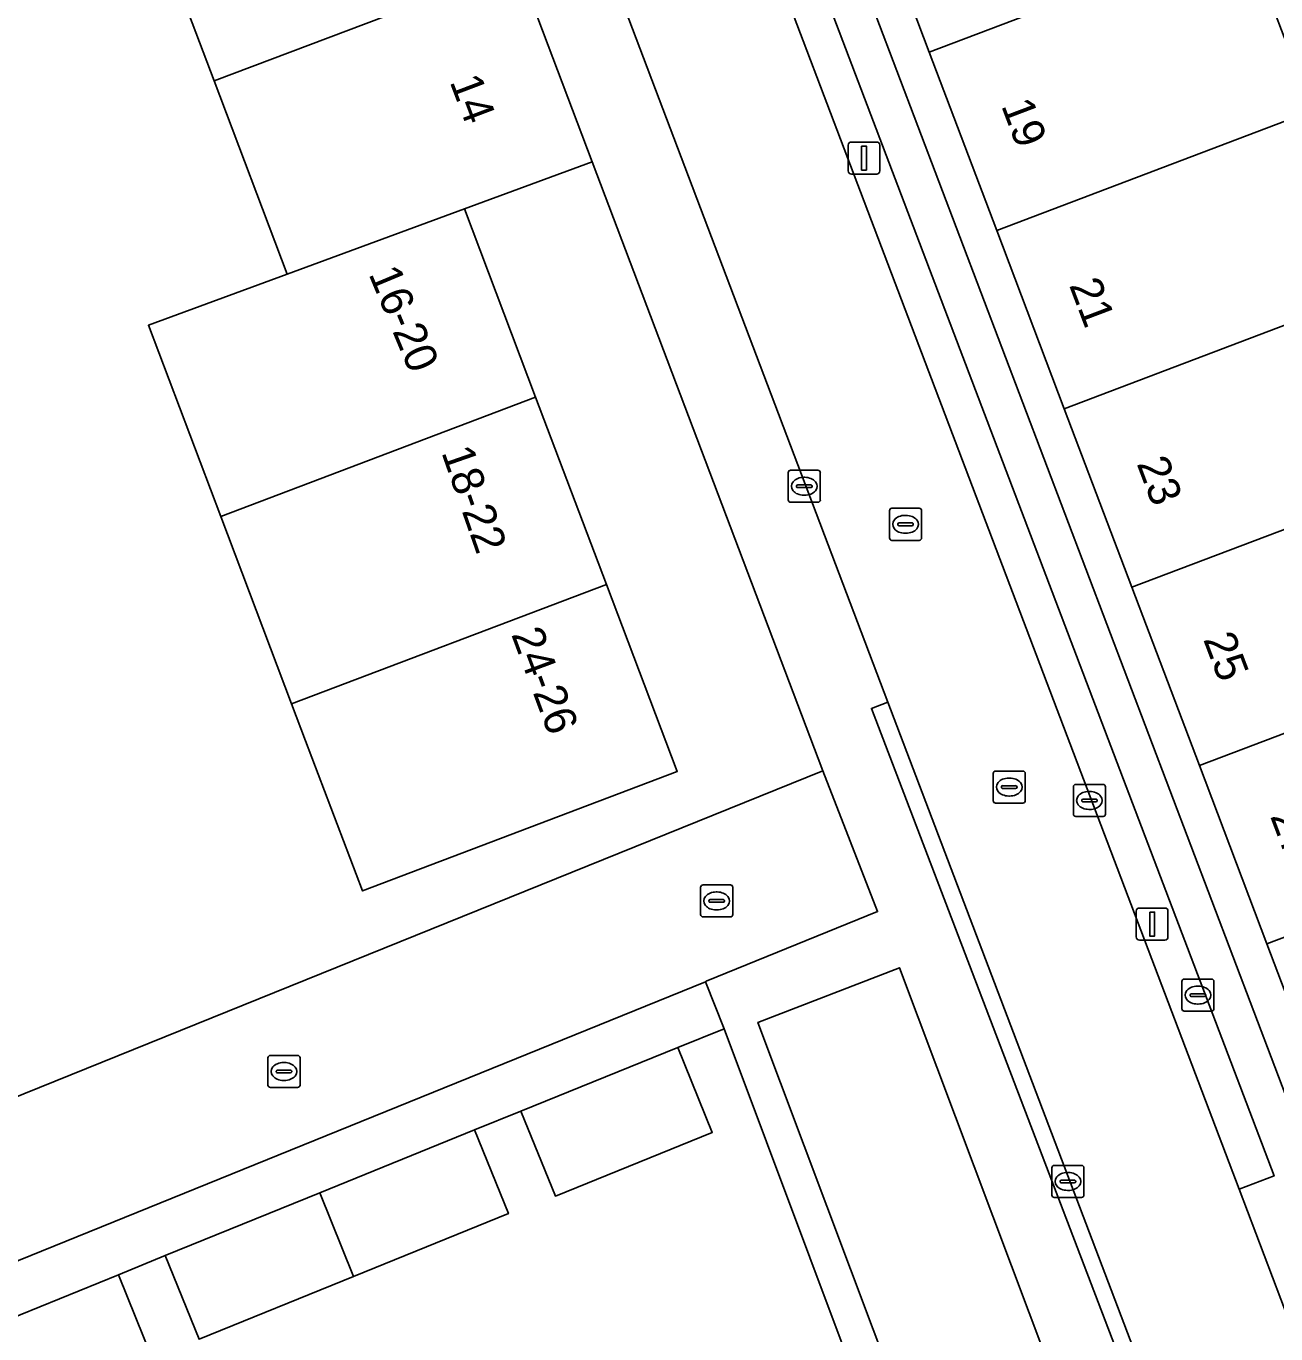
# Model space of a CAD drawing. Extents: x 162989 to 165008, y 383432 to 384338.
# Drawn here: x 163905.52 to 163944.51, y 384017.83 to 384058.61 of the extents above; entities that cross this region are included whole.
import ezdxf

# ---------------------------------------------------------------- set-up
doc = ezdxf.new("R2010")
doc.units = 0
for name, color, linetype in [('IMGEO_Brandkraan', 7, 'Continuous'), ('IMGEO_Erf', 7, 'Continuous'), ('IMGEO_Groenvoorziening', 7, 'Continuous'), ('IMGEO_Kolk', 7, 'Continuous'), ('IMGEO_Lichtmast', 7, 'Continuous'), ('IMGEO_Pand', 7, 'Continuous'), ('IMGEO_Pand_nummerreeks', 7, 'Continuous'), ('IMGEO_Parkeervlak_open', 7, 'Continuous'), ('IMGEO_Rijbaan_lokaal_open', 7, 'Continuous'), ('IMGEO_Rioolput', 7, 'Continuous'), ('IMGEO_Voetpad_open', 7, 'Continuous')]:
    doc.layers.add(name, color=color, linetype=linetype)

msp = doc.modelspace()

# ---------------------------------------------------------------- linework, layer by layer
at = {"layer": 'IMGEO_Brandkraan'}
for p, q in [((163941.655, 384028.894), (163942.507, 384028.894)), ((163941.58, 384027.968), (163941.58, 384028.82)), ((163941.882, 384028.437), (163942.28, 384028.437)), ((163942.068, 384028.674), (163942.093, 384028.674)), ((163942.581, 384028.82), (163942.581, 384027.968)), ((163941.839, 384028.388), (163941.839, 384028.4)), ((163942.277, 384028.351), (163941.879, 384028.351)), ((163942.091, 384028.114), (163942.066, 384028.114)), ((163942.323, 384028.4), (163942.323, 384028.388)), ((163942.507, 384027.894), (163941.655, 384027.894))]:
    msp.add_line(p, q, dxfattribs=at)
for points in [[(163941.655, 384028.894), (163942.507, 384028.894)], [(163941.58, 384027.968), (163941.58, 384028.82)], [(163942.581, 384028.82), (163942.581, 384027.968)], [(163942.507, 384027.894), (163941.655, 384027.894)]]:
    msp.add_lwpolyline(points, dxfattribs=at)
for centre, radius, start, end in [((163941.657, 384028.818), 0.0765, 91.552, 178.448), ((163941.657, 384028.818), 0.0765, 91.552, 178.448), ((163942.505, 384028.818), 0.0765, 1.552, 88.448), ((163942.505, 384028.818), 0.0765, 1.552, 88.448), ((163941.879, 384028.397), 0.0403, 85.8775, 175.7526), ((163942.284, 384028.399), 0.0386, 1.7309, 96.639), ((163941.876, 384028.387), 0.0366, 178.938, 274.7102), ((163942.28, 384028.394), 0.043, 264.8664, 352.4533), ((163941.657, 384027.97), 0.0765, 181.552, 268.448), ((163941.657, 384027.97), 0.0765, 181.552, 268.448), ((163942.505, 384027.97), 0.0765, 271.552, 358.448), ((163942.505, 384027.97), 0.0765, 271.552, 358.448)]:
    msp.add_arc(centre, radius, start, end, dxfattribs=at)
for centre, major_axis, ratio, start_param, end_param in [((163942.067, 384028.394), (-0.387, 0.002), 0.722429, 4.712389, 7.853982), ((163942.092, 384028.394), (-0.39, 0.002), 0.717154, 1.570796, 4.712389)]:
    msp.add_ellipse(centre, major_axis=major_axis, ratio=ratio, start_param=start_param, end_param=end_param, dxfattribs=at)
at = {"layer": 'IMGEO_Erf'}
for points in [[(163944.693, 384087.722), (163943.187, 384090.664), (163940.668, 384096.069), (163940.042, 384097.411), (163938.387, 384100.469), (163933.086, 384111.619), (163931.815, 384114.219), (163930.51, 384116.89), (163930.356, 384117.204), (163925.265, 384126.849), (163923.141, 384131.213), (163919.387, 384130.435), (163918.639, 384132.305), (163909.406, 384130.442), (163905.997, 384128.384), (163911.891, 384112.19), (163917.32, 384097.768), (163932.033, 384058.943), (163947.096, 384019.256)], [(163946.338, 384024.426), (163944.232, 384029.99), (163942.125, 384035.553), (163940.018, 384041.116), (163937.911, 384046.679), (163935.805, 384052.243), (163933.698, 384057.806), (163931.591, 384063.369), (163931.262, 384063.247), (163931.112, 384063.649), (163941.553, 384067.621), (163941.705, 384067.219), (163941.424, 384067.112), (163943.537, 384061.532), (163945.643, 384055.968)], [(163902.507, 384024.128), (163930.377, 384035.386), (163923.18, 384054.38), (163919.194, 384052.913), (163921.417, 384047.039), (163923.627, 384041.2), (163925.836, 384035.362), (163916.01, 384031.643), (163914.24, 384036.32), (163913.8, 384037.482), (163911.591, 384043.32), (163909.334, 384049.285), (163913.666, 384050.879), (163911.386, 384056.903), (163909.242, 384062.567)], [(163935.283, 384006.035), (163927.294, 384027.344), (163925.849, 384026.763), (163926.926, 384024.111), (163922.034, 384022.124), (163920.957, 384024.777), (163919.506, 384024.19), (163920.565, 384021.579), (163915.736, 384019.618), (163910.914, 384017.661), (163909.854, 384020.271), (163908.4, 384019.665), (163909.465, 384017.041)]]:
    msp.add_lwpolyline(points, dxfattribs=at)
at = {"layer": 'IMGEO_Groenvoorziening'}
msp.add_lwpolyline([(163929.171, 384062.968), (163928.089, 384062.572), (163943.363, 384022.339), (163944.456, 384022.755)], close=True, dxfattribs=at)
at = {"layer": 'IMGEO_Kolk'}
for p, q in [((163929.373, 384044.763), (163930.225, 384044.763)), ((163929.298, 384043.837), (163929.298, 384044.689)), ((163929.786, 384044.543), (163929.811, 384044.543)), ((163930.299, 384044.689), (163930.299, 384043.837)), ((163929.557, 384044.257), (163929.557, 384044.269)), ((163929.995, 384044.22), (163929.597, 384044.22)), ((163929.6, 384044.306), (163929.998, 384044.306)), ((163929.809, 384043.983), (163929.784, 384043.983)), ((163930.041, 384044.269), (163930.041, 384044.257)), ((163930.225, 384043.763), (163929.373, 384043.763)), ((163938.27, 384034.964), (163939.122, 384034.964)), ((163938.195, 384034.038), (163938.195, 384034.89)), ((163938.683, 384034.744), (163938.708, 384034.744)), ((163939.196, 384034.89), (163939.196, 384034.038)), ((163938.454, 384034.458), (163938.454, 384034.47)), ((163938.892, 384034.421), (163938.494, 384034.421)), ((163938.497, 384034.507), (163938.895, 384034.507)), ((163938.706, 384034.184), (163938.681, 384034.184)), ((163938.938, 384034.47), (163938.938, 384034.458)), ((163939.122, 384033.964), (163938.27, 384033.964)), ((163926.564, 384030.904), (163926.564, 384031.756)), ((163926.639, 384031.83), (163927.491, 384031.83)), ((163927.565, 384031.756), (163927.565, 384030.904)), ((163926.823, 384031.324), (163926.823, 384031.336)), ((163927.261, 384031.287), (163926.863, 384031.287)), ((163926.866, 384031.373), (163927.264, 384031.373)), ((163927.052, 384031.61), (163927.077, 384031.61)), ((163927.307, 384031.336), (163927.307, 384031.324)), ((163927.075, 384031.05), (163927.05, 384031.05)), ((163927.491, 384030.83), (163926.639, 384030.83)), ((163913.064, 384025.585), (163913.064, 384026.437)), ((163913.139, 384026.511), (163913.991, 384026.511)), ((163914.065, 384026.437), (163914.065, 384025.585)), ((163913.323, 384026.005), (163913.323, 384026.017)), ((163913.366, 384026.054), (163913.764, 384026.054)), ((163913.552, 384026.291), (163913.577, 384026.291)), ((163913.807, 384026.017), (163913.807, 384026.005)), ((163913.761, 384025.968), (163913.363, 384025.968)), ((163913.575, 384025.731), (163913.55, 384025.731)), ((163913.991, 384025.511), (163913.139, 384025.511)), ((163937.524, 384022.156), (163937.524, 384023.008)), ((163937.599, 384023.082), (163938.451, 384023.082)), ((163938.012, 384022.862), (163938.037, 384022.862)), ((163938.525, 384023.008), (163938.525, 384022.156)), ((163937.783, 384022.576), (163937.783, 384022.588)), ((163938.221, 384022.539), (163937.823, 384022.539)), ((163937.826, 384022.625), (163938.224, 384022.625)), ((163938.267, 384022.588), (163938.267, 384022.576)), ((163938.451, 384022.082), (163937.599, 384022.082)), ((163938.035, 384022.302), (163938.01, 384022.302))]:
    msp.add_line(p, q, dxfattribs=at)
for points in [[(163929.373, 384044.763), (163930.225, 384044.763)], [(163929.298, 384043.837), (163929.298, 384044.689)], [(163930.299, 384044.689), (163930.299, 384043.837)], [(163930.225, 384043.763), (163929.373, 384043.763)], [(163938.27, 384034.964), (163939.122, 384034.964)], [(163938.195, 384034.038), (163938.195, 384034.89)], [(163939.196, 384034.89), (163939.196, 384034.038)], [(163939.122, 384033.964), (163938.27, 384033.964)], [(163926.564, 384030.904), (163926.564, 384031.756)], [(163926.639, 384031.83), (163927.491, 384031.83)], [(163927.565, 384031.756), (163927.565, 384030.904)], [(163927.491, 384030.83), (163926.639, 384030.83)], [(163913.064, 384025.585), (163913.064, 384026.437)], [(163913.139, 384026.511), (163913.991, 384026.511)], [(163914.065, 384026.437), (163914.065, 384025.585)], [(163913.991, 384025.511), (163913.139, 384025.511)], [(163937.524, 384022.156), (163937.524, 384023.008)], [(163937.599, 384023.082), (163938.451, 384023.082)], [(163938.525, 384023.008), (163938.525, 384022.156)], [(163938.451, 384022.082), (163937.599, 384022.082)]]:
    msp.add_lwpolyline(points, dxfattribs=at)
for centre, radius, start, end in [((163929.375, 384044.687), 0.0765, 91.552, 178.448), ((163929.375, 384044.687), 0.0765, 91.552, 178.448), ((163930.223, 384044.687), 0.0765, 1.552, 88.448), ((163930.223, 384044.687), 0.0765, 1.552, 88.448), ((163929.597, 384044.266), 0.0403, 85.8775, 175.7526), ((163929.594, 384044.256), 0.0366, 178.938, 274.7102), ((163929.998, 384044.263), 0.043, 264.8664, 352.4533), ((163930.002, 384044.268), 0.0386, 1.7309, 96.639), ((163929.375, 384043.839), 0.0765, 181.552, 268.448), ((163929.375, 384043.839), 0.0765, 181.552, 268.448), ((163930.223, 384043.839), 0.0765, 271.552, 358.448), ((163930.223, 384043.839), 0.0765, 271.552, 358.448), ((163938.272, 384034.888), 0.0765, 91.552, 178.448), ((163938.272, 384034.888), 0.0765, 91.552, 178.448), ((163939.12, 384034.888), 0.0765, 1.552, 88.448), ((163939.12, 384034.888), 0.0765, 1.552, 88.448), ((163938.494, 384034.467), 0.0403, 85.8775, 175.7526), ((163938.491, 384034.457), 0.0366, 178.938, 274.7102), ((163938.895, 384034.464), 0.043, 264.8664, 352.4533), ((163938.899, 384034.469), 0.0386, 1.7309, 96.639), ((163938.272, 384034.04), 0.0765, 181.552, 268.448), ((163938.272, 384034.04), 0.0765, 181.552, 268.448), ((163939.12, 384034.04), 0.0765, 271.552, 358.448), ((163939.12, 384034.04), 0.0765, 271.552, 358.448), ((163926.641, 384031.754), 0.0765, 91.552, 178.448), ((163926.641, 384031.754), 0.0765, 91.552, 178.448), ((163927.489, 384031.754), 0.0765, 1.552, 88.448), ((163927.489, 384031.754), 0.0765, 1.552, 88.448), ((163926.863, 384031.333), 0.0403, 85.8775, 175.7526), ((163926.86, 384031.323), 0.0366, 178.938, 274.7102), ((163927.264, 384031.33), 0.043, 264.8664, 352.4533), ((163927.268, 384031.335), 0.0386, 1.7309, 96.639), ((163926.641, 384030.906), 0.0765, 181.552, 268.448), ((163926.641, 384030.906), 0.0765, 181.552, 268.448), ((163927.489, 384030.906), 0.0765, 271.552, 358.448), ((163927.489, 384030.906), 0.0765, 271.552, 358.448), ((163913.141, 384026.435), 0.0765, 91.552, 178.448), ((163913.141, 384026.435), 0.0765, 91.552, 178.448), ((163913.989, 384026.435), 0.0765, 1.552, 88.448), ((163913.989, 384026.435), 0.0765, 1.552, 88.448), ((163913.363, 384026.014), 0.0403, 85.8775, 175.7526), ((163913.36, 384026.004), 0.0366, 178.938, 274.7102), ((163913.764, 384026.011), 0.043, 264.8664, 352.4533), ((163913.768, 384026.016), 0.0386, 1.7309, 96.639), ((163913.141, 384025.587), 0.0765, 181.552, 268.448), ((163913.141, 384025.587), 0.0765, 181.552, 268.448), ((163913.989, 384025.587), 0.0765, 271.552, 358.448), ((163913.989, 384025.587), 0.0765, 271.552, 358.448), ((163937.601, 384023.006), 0.0765, 91.552, 178.448), ((163937.601, 384023.006), 0.0765, 91.552, 178.448), ((163938.449, 384023.006), 0.0765, 1.552, 88.448), ((163938.449, 384023.006), 0.0765, 1.552, 88.448), ((163937.823, 384022.585), 0.0403, 85.8775, 175.7526), ((163937.82, 384022.575), 0.0366, 178.938, 274.7102), ((163938.224, 384022.582), 0.043, 264.8664, 352.4533), ((163938.228, 384022.587), 0.0386, 1.7309, 96.639), ((163937.601, 384022.158), 0.0765, 181.552, 268.448), ((163937.601, 384022.158), 0.0765, 181.552, 268.448), ((163938.449, 384022.158), 0.0765, 271.552, 358.448), ((163938.449, 384022.158), 0.0765, 271.552, 358.448)]:
    msp.add_arc(centre, radius, start, end, dxfattribs=at)
for centre, major_axis, ratio, start_param, end_param in [((163929.785, 384044.263), (-0.387, 0.002), 0.722429, 4.712389, 7.853982), ((163929.81, 384044.263), (-0.39, 0.002), 0.717154, 1.570796, 4.712389), ((163938.682, 384034.464), (-0.387, 0.002), 0.722429, 4.712389, 7.853982), ((163938.707, 384034.464), (-0.39, 0.002), 0.717154, 1.570796, 4.712389), ((163927.051, 384031.33), (-0.387, 0.002), 0.722429, 4.712389, 7.853982), ((163927.076, 384031.33), (-0.39, 0.002), 0.717154, 1.570796, 4.712389), ((163913.551, 384026.011), (-0.387, 0.002), 0.722429, 4.712389, 7.853982), ((163913.576, 384026.011), (-0.39, 0.002), 0.717154, 1.570796, 4.712389), ((163938.011, 384022.582), (-0.387, 0.002), 0.722429, 4.712389, 7.853982), ((163938.036, 384022.582), (-0.39, 0.002), 0.717154, 1.570796, 4.712389)]:
    msp.add_ellipse(centre, major_axis=major_axis, ratio=ratio, start_param=start_param, end_param=end_param, dxfattribs=at)
at = {"layer": 'IMGEO_Lichtmast'}
for p, q in [((163931.267, 384054.999), (163932.057, 384054.999)), ((163932.057, 384054.999), (163931.267, 384054.999)), ((163931.167, 384054.099), (163931.167, 384054.899)), ((163931.167, 384054.899), (163931.167, 384054.099)), ((163932.157, 384054.899), (163932.157, 384054.099)), ((163932.157, 384054.099), (163932.157, 384054.899)), ((163932.057, 384053.999), (163931.267, 384053.999)), ((163931.267, 384053.999), (163932.057, 384053.999)), ((163940.156, 384030.209), (163940.156, 384031.009)), ((163940.156, 384031.009), (163940.156, 384030.209)), ((163940.256, 384031.109), (163941.046, 384031.109)), ((163941.046, 384031.109), (163940.256, 384031.109)), ((163941.146, 384031.009), (163941.146, 384030.209)), ((163941.146, 384030.209), (163941.146, 384031.009)), ((163941.046, 384030.109), (163940.256, 384030.109)), ((163940.256, 384030.109), (163941.046, 384030.109))]:
    msp.add_line(p, q, dxfattribs=at)
for points in [[(163931.587, 384054.874), (163931.737, 384054.874), (163931.737, 384054.124), (163931.587, 384054.124), (163931.587, 384054.874)], [(163940.576, 384030.984), (163940.726, 384030.984), (163940.726, 384030.234), (163940.576, 384030.234), (163940.576, 384030.984)]]:
    msp.add_lwpolyline(points, dxfattribs=at)
for centre, start, end in [((163931.267, 384054.899), 90, 180), ((163931.267, 384054.899), 90, 180), ((163932.057, 384054.899), 0, 90), ((163932.057, 384054.899), 360, 90), ((163931.267, 384054.099), 180, 270), ((163931.267, 384054.099), 180, 270), ((163932.057, 384054.099), 270, 0), ((163932.057, 384054.099), 270, 0), ((163940.256, 384031.009), 90, 180), ((163940.256, 384031.009), 90, 180), ((163941.046, 384031.009), 0, 90), ((163941.046, 384031.009), 360, 90), ((163940.256, 384030.209), 180, 270), ((163940.256, 384030.209), 180, 270), ((163941.046, 384030.209), 270, 0), ((163941.046, 384030.209), 270, 0)]:
    msp.add_arc(centre, 0.1, start, end, dxfattribs=at)
at = {"layer": 'IMGEO_Pand'}
for points in [[(163941.424, 384067.112), (163941.705, 384067.219), (163941.553, 384067.621), (163931.112, 384063.649), (163931.262, 384063.247), (163931.591, 384063.369), (163933.698, 384057.806), (163943.537, 384061.532)], [(163918.72, 384066.164), (163909.49, 384062.657), (163909.242, 384062.567), (163911.386, 384056.903), (163920.867, 384060.492)], [(163943.537, 384061.532), (163933.698, 384057.806), (163935.805, 384052.243), (163945.643, 384055.968)], [(163920.867, 384060.492), (163911.386, 384056.903), (163913.666, 384050.879), (163919.194, 384052.913), (163923.18, 384054.38)], [(163945.643, 384055.968), (163935.805, 384052.243), (163937.911, 384046.679), (163947.749, 384050.405)], [(163919.194, 384052.913), (163913.666, 384050.879), (163909.334, 384049.285), (163911.591, 384043.32), (163921.417, 384047.039)], [(163947.749, 384050.405), (163937.911, 384046.679), (163940.018, 384041.116), (163949.856, 384044.841)], [(163921.417, 384047.039), (163911.591, 384043.32), (163913.8, 384037.482), (163923.627, 384041.2)], [(163949.856, 384044.841), (163940.018, 384041.116), (163942.125, 384035.553), (163951.962, 384039.278)], [(163913.8, 384037.482), (163914.24, 384036.32), (163916.01, 384031.643), (163925.836, 384035.362), (163923.627, 384041.2)], [(163951.962, 384039.278), (163942.125, 384035.553), (163944.232, 384029.99), (163954.068, 384033.715)], [(163954.068, 384033.715), (163944.232, 384029.99), (163946.338, 384024.426), (163956.175, 384028.151)], [(163922.034, 384022.124), (163926.926, 384024.111), (163925.849, 384026.763), (163920.957, 384024.777)], [(163915.736, 384019.618), (163920.565, 384021.579), (163919.506, 384024.19), (163914.679, 384022.23)], [(163915.736, 384019.618), (163914.679, 384022.23), (163909.854, 384020.271), (163910.914, 384017.661)], [(163908.4, 384019.665), (163903.482, 384017.669), (163904.546, 384015.044), (163905.667, 384012.278), (163907.403, 384012.982), (163906.282, 384015.749), (163909.465, 384017.041)]]:
    msp.add_lwpolyline(points, close=True, dxfattribs=at)
at = {"layer": 'IMGEO_Parkeervlak_open'}
msp.add_lwpolyline([(163932.772, 384029.248), (163928.351, 384027.544), (163936.28, 384006.427), (163938.328, 384007.232), (163940.698, 384008.164), (163940.314, 384009.185)], close=True, dxfattribs=at)
at = {"layer": 'IMGEO_Rijbaan_lokaal_open'}
for points in [[(163902.699, 384136.428), (163902.42, 384136.156), (163900.713, 384134.073), (163899.073, 384131.221), (163898.552, 384127.219), (163903.65, 384113.577), (163905.658, 384108.202), (163908.244, 384101.283), (163909.453, 384098.047), (163932.403, 384037.527), (163941.155, 384014.522), (163945.705, 384016.169), (163943.363, 384022.339), (163928.089, 384062.572), (163925.404, 384069.644), (163909.585, 384111.313)], [(163883.455, 384011.268), (163926.713, 384028.812), (163926.74, 384028.823), (163932.083, 384030.999), (163930.377, 384035.386), (163902.507, 384024.128), (163901.478, 384026.314), (163897.702, 384025.039), (163894.578, 384023.985), (163891.454, 384022.93), (163888.33, 384021.875), (163885.206, 384020.821), (163882.179, 384019.799), (163881.986, 384020.303), (163881.907, 384020.275), (163878.85, 384019.212), (163878.058, 384021.439), (163874.697, 384020.022), (163871.44, 384018.648), (163870.896, 384019.938), (163867.897, 384018.685), (163866.698, 384016.124)]]:
    msp.add_lwpolyline(points, dxfattribs=at)
at = {"layer": 'IMGEO_Rioolput'}
for p, q in [((163932.532, 384043.576), (163933.384, 384043.576)), ((163932.457, 384042.65), (163932.457, 384043.502)), ((163932.759, 384043.119), (163933.157, 384043.119)), ((163932.945, 384043.356), (163932.97, 384043.356)), ((163933.458, 384043.502), (163933.458, 384042.65)), ((163932.716, 384043.07), (163932.716, 384043.082)), ((163933.154, 384043.033), (163932.756, 384043.033)), ((163932.968, 384042.796), (163932.943, 384042.796)), ((163933.2, 384043.082), (163933.2, 384043.07)), ((163933.384, 384042.576), (163932.532, 384042.576)), ((163935.768, 384035.382), (163936.62, 384035.382)), ((163935.693, 384034.456), (163935.693, 384035.308)), ((163936.181, 384035.162), (163936.206, 384035.162)), ((163936.694, 384035.308), (163936.694, 384034.456)), ((163935.952, 384034.876), (163935.952, 384034.888)), ((163936.39, 384034.839), (163935.992, 384034.839)), ((163935.995, 384034.925), (163936.393, 384034.925)), ((163936.204, 384034.602), (163936.179, 384034.602)), ((163936.436, 384034.888), (163936.436, 384034.876)), ((163936.62, 384034.382), (163935.768, 384034.382))]:
    msp.add_line(p, q, dxfattribs=at)
for points in [[(163932.532, 384043.576), (163933.384, 384043.576)], [(163932.457, 384042.65), (163932.457, 384043.502)], [(163933.458, 384043.502), (163933.458, 384042.65)], [(163933.384, 384042.576), (163932.532, 384042.576)], [(163935.768, 384035.382), (163936.62, 384035.382)], [(163935.693, 384034.456), (163935.693, 384035.308)], [(163936.694, 384035.308), (163936.694, 384034.456)], [(163936.62, 384034.382), (163935.768, 384034.382)]]:
    msp.add_lwpolyline(points, dxfattribs=at)
for centre, radius, start, end in [((163932.534, 384043.5), 0.0765, 91.552, 178.448), ((163932.534, 384043.5), 0.0765, 91.552, 178.448), ((163933.382, 384043.5), 0.0765, 1.552, 88.448), ((163933.382, 384043.5), 0.0765, 1.552, 88.448), ((163932.756, 384043.079), 0.0403, 85.8775, 175.7526), ((163933.161, 384043.081), 0.0386, 1.7309, 96.639), ((163932.753, 384043.069), 0.0366, 178.938, 274.7102), ((163933.157, 384043.076), 0.043, 264.8664, 352.4533), ((163932.534, 384042.652), 0.0765, 181.552, 268.448), ((163932.534, 384042.652), 0.0765, 181.552, 268.448), ((163933.382, 384042.652), 0.0765, 271.552, 358.448), ((163933.382, 384042.652), 0.0765, 271.552, 358.448), ((163935.77, 384035.306), 0.0765, 91.552, 178.448), ((163935.77, 384035.306), 0.0765, 91.552, 178.448), ((163936.618, 384035.306), 0.0765, 1.552, 88.448), ((163936.618, 384035.306), 0.0765, 1.552, 88.448), ((163935.992, 384034.885), 0.0403, 85.8775, 175.7526), ((163935.989, 384034.875), 0.0366, 178.938, 274.7102), ((163936.393, 384034.882), 0.043, 264.8664, 352.4533), ((163936.397, 384034.887), 0.0386, 1.7309, 96.639), ((163935.77, 384034.458), 0.0765, 181.552, 268.448), ((163935.77, 384034.458), 0.0765, 181.552, 268.448), ((163936.618, 384034.458), 0.0765, 271.552, 358.448), ((163936.618, 384034.458), 0.0765, 271.552, 358.448)]:
    msp.add_arc(centre, radius, start, end, dxfattribs=at)
for centre, major_axis, ratio, start_param, end_param in [((163932.944, 384043.076), (-0.387, 0.002), 0.722429, 4.712389, 7.853982), ((163932.969, 384043.076), (-0.39, 0.002), 0.717154, 1.570796, 4.712389), ((163936.18, 384034.882), (-0.387, 0.002), 0.722429, 4.712389, 7.853982), ((163936.205, 384034.882), (-0.39, 0.002), 0.717154, 1.570796, 4.712389)]:
    msp.add_ellipse(centre, major_axis=major_axis, ratio=ratio, start_param=start_param, end_param=end_param, dxfattribs=at)
at = {"layer": 'IMGEO_Voetpad_open'}
for points in [[(163932.033, 384058.943), (163917.32, 384097.768), (163911.891, 384112.19), (163910.739, 384111.752), (163916.167, 384097.33), (163926.518, 384070.073), (163925.404, 384069.644), (163928.089, 384062.572), (163929.171, 384062.968), (163944.456, 384022.755), (163943.363, 384022.339), (163945.705, 384016.169), (163947.266, 384012.058), (163948.608, 384008.523)], [(163944.247, 384006.394), (163943.847, 384007.446), (163943.376, 384007.266), (163942.325, 384010.017), (163931.891, 384037.332), (163932.403, 384037.527), (163909.453, 384098.047)], [(163920.867, 384060.492), (163923.18, 384054.38), (163930.377, 384035.386), (163932.083, 384030.999), (163926.74, 384028.823), (163926.713, 384028.812), (163927.294, 384027.344), (163935.283, 384006.035), (163936.28, 384006.427), (163928.351, 384027.544), (163932.772, 384029.248), (163940.314, 384009.185), (163940.698, 384008.164), (163938.328, 384007.232), (163938.547, 384006.674), (163938.767, 384006.115), (163939.919, 384003.04), (163941.121, 384000), (163944.428, 384001.499)], [(163948.429, 384015.677), (163947.541, 384018.062), (163947.096, 384019.256), (163932.033, 384058.943)], [(163903.482, 384017.669), (163908.4, 384019.665), (163909.854, 384020.271), (163914.679, 384022.23), (163919.506, 384024.19), (163920.957, 384024.777), (163925.849, 384026.763), (163927.294, 384027.344), (163926.713, 384028.812), (163883.455, 384011.268)]]:
    msp.add_lwpolyline(points, dxfattribs=at)
msp.add_lwpolyline([(163932.403, 384037.527), (163931.891, 384037.332), (163942.325, 384010.017), (163943.376, 384007.266), (163943.847, 384007.446), (163941.155, 384014.522)], close=True, dxfattribs=at)

# ---------------------------------------------------------------- texts
at = {"layer": 'IMGEO_Pand_nummerreeks'}
for s, rotation, p in [('14', 290.7294, (163918.725, 384056.884)), ('19', 290.7409, (163935.933, 384056.138)), ('16-20', 292.6202, (163916.195, 384050.889)), ('21', 290.7409, (163938.054, 384050.536)), ('18-22', 289.2593, (163918.469, 384045.322)), ('23', 290.7409, (163940.161, 384044.973)), ('24-26', 290.4099, (163920.647, 384039.648)), ('25', 290.7409, (163942.237, 384039.492)), ('27', 290.7409, (163944.325, 384033.977))]:
    msp.add_text(s, height=1, rotation=rotation, dxfattribs=at).set_placement(p)

doc.saveas('drawing.dxf')
